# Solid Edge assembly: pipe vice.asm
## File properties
Author: CADCIM
Template: Iso Assembly.asm
Last saved by: TIET
Revision: 8
Application: Solid Edge
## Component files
base.par
Screw.par
moveable jaw.par
handle.par
handle screw.par
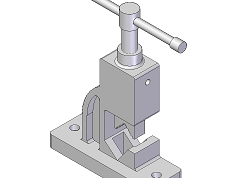
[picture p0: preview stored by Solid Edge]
